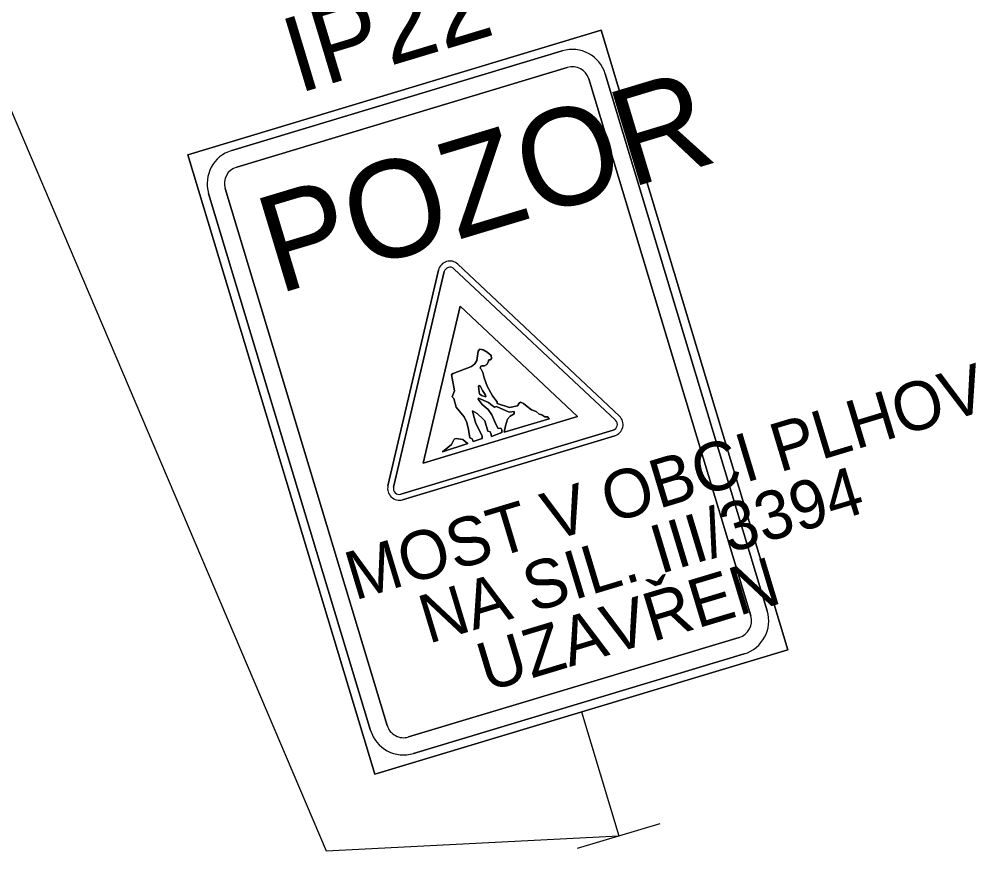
# Model space of a CAD drawing. Extents: x -688893 to -679983, y -1088371 to -1075771.
# Drawn here: x -686908 to -686243, y -1079689 to -1079111 of the extents above; entities that cross this region are included whole.
import ezdxf

# ---------------------------------------------------------------- set-up
doc = ezdxf.new("R2010")
doc.units = 0
for name, color, linetype in [('SDZ', 7, 'Continuous'), ('SDZ ozn', 7, 'Continuous'), ('SDZ plochy', 7, 'Continuous'), ('SDZ symbol', 7, 'Continuous')]:
    doc.layers.add(name, color=color, linetype=linetype)

msp = doc.modelspace()

# ---------------------------------------------------------------- linework, layer by layer
at = {"layer": 'SDZ'}
for p, q in [((-686790.82, -1079204.92), (-686503.59, -1079118.31)), ((-686503.59, -1079118.31), (-686373.67, -1079549.15)), ((-686760.36, -1079202.01), (-686530.58, -1079132.72)), ((-686756.9, -1079213.5), (-686527.12, -1079144.21)), ((-686500.67, -1079148.77), (-686388.08, -1079522.16)), ((-686512.16, -1079152.23), (-686399.57, -1079525.62)), ((-686660.9, -1079635.76), (-686790.82, -1079204.92)), ((-686652.33, -1079601.84), (-686764.92, -1079228.45)), ((-686663.82, -1079605.31), (-686776.41, -1079231.91)), ((-686603.16, -1079281.06), (-686490.86, -1079386.71)), ((-686603.06, -1079281.16), (-686603.06, -1079281.16)), ((-686651.78, -1079435.24), (-686616.6, -1079285.11)), ((-686612.59, -1079286.26), (-686647.9, -1079436.18)), ((-686612.56, -1079286.14), (-686612.56, -1079286.14)), ((-686493.57, -1079389.64), (-686605.87, -1079284.24)), ((-686601.66, -1079310.35), (-686627.36, -1079419.41)), ((-686519.95, -1079387.02), (-686601.66, -1079310.35)), ((-686589.05, -1079341.65), (-686589.59, -1079344.78)), ((-686587.79, -1079340.22), (-686589.05, -1079341.65)), ((-686585.56, -1079340.6), (-686587.79, -1079340.22)), ((-686582.72, -1079342.29), (-686585.56, -1079340.6)), ((-686589.87, -1079348.04), (-686591.29, -1079350.37)), ((-686589.59, -1079344.78), (-686589.87, -1079348.04)), ((-686580.1, -1079344.67), (-686582.72, -1079342.29)), ((-686582.09, -1079349.29), (-686581.53, -1079347.64)), ((-686581.53, -1079347.64), (-686580.51, -1079347.54)), ((-686580.51, -1079347.54), (-686579.71, -1079346.67)), ((-686579.71, -1079346.67), (-686580.1, -1079344.67)), ((-686593.71, -1079352.15), (-686606.41, -1079357.04)), ((-686591.29, -1079350.37), (-686593.71, -1079352.15)), ((-686587.65, -1079353.29), (-686587.23, -1079351.89)), ((-686586.97, -1079354.14), (-686587.65, -1079353.29)), ((-686587.23, -1079351.89), (-686586.45, -1079351.66)), ((-686585.89, -1079356.35), (-686586.97, -1079354.14)), ((-686586.45, -1079351.66), (-686584.73, -1079351.77)), ((-686584.73, -1079351.77), (-686583.1, -1079350.86)), ((-686583.1, -1079350.86), (-686582.09, -1079349.29)), ((-686606.41, -1079357.04), (-686607.65, -1079357.84)), ((-686607.65, -1079357.84), (-686605.48, -1079369.24)), ((-686584.77, -1079360.04), (-686585.89, -1079356.35)), ((-686582.77, -1079365.99), (-686584.77, -1079360.04)), ((-686588.26, -1079365.32), (-686588.86, -1079366.13)), ((-686588.86, -1079366.13), (-686588.39, -1079369.8)), ((-686587.38, -1079366.11), (-686588.26, -1079365.32)), ((-686585.93, -1079368.84), (-686587.38, -1079366.11)), ((-686579.11, -1079372.5), (-686582.77, -1079365.99)), ((-686605.48, -1079369.24), (-686607.2, -1079373.35)), ((-686607.2, -1079373.35), (-686606.01, -1079374.48)), ((-686606.01, -1079374.48), (-686604.39, -1079380.55)), ((-686588.98, -1079374.84), (-686588.71, -1079374.34)), ((-686586.34, -1079378.7), (-686588.98, -1079374.84)), ((-686588.71, -1079374.34), (-686581.88, -1079377.35)), ((-686588.39, -1079369.8), (-686588.17, -1079371.21)), ((-686588.17, -1079371.21), (-686586.74, -1079372.47)), ((-686586.74, -1079372.47), (-686583.75, -1079373.26)), ((-686584.21, -1079371.71), (-686585.93, -1079368.84)), ((-686583.75, -1079373.26), (-686584.21, -1079371.71)), ((-686576.96, -1079375.45), (-686579.11, -1079372.5)), ((-686604.39, -1079380.55), (-686602.16, -1079383.05)), ((-686582.14, -1079382.09), (-686586.34, -1079378.7)), ((-686581.88, -1079377.35), (-686580.19, -1079378.75)), ((-686580.19, -1079378.75), (-686577.74, -1079380.55)), ((-686577.74, -1079380.55), (-686576.19, -1079380.08)), ((-686575.91, -1079376.82), (-686576.96, -1079375.45)), ((-686576.19, -1079380.08), (-686567.4, -1079383.99)), ((-686575.75, -1079378.04), (-686575.91, -1079376.82)), ((-686567.31, -1079380.78), (-686575.75, -1079378.04)), ((-686561.76, -1079379.54), (-686567.31, -1079380.78)), ((-686560.62, -1079377.71), (-686561.76, -1079379.54)), ((-686559.57, -1079376.97), (-686560.62, -1079377.71)), ((-686557.56, -1079378.06), (-686559.57, -1079376.97)), ((-686554.86, -1079379.99), (-686557.56, -1079378.06)), ((-686551.85, -1079382.26), (-686554.86, -1079379.99)), ((-686627.36, -1079419.41), (-686519.95, -1079387.02)), ((-686602.16, -1079383.05), (-686598.82, -1079387.11)), ((-686598.82, -1079387.11), (-686596.95, -1079391.2)), ((-686592.38, -1079386.02), (-686592.87, -1079382.99)), ((-686592.87, -1079382.99), (-686589.78, -1079384.81)), ((-686590.63, -1079391.83), (-686592.38, -1079386.02)), ((-686589.78, -1079384.81), (-686585.61, -1079388.84)), ((-686579.56, -1079385.75), (-686582.14, -1079382.09)), ((-686577.4, -1079390.81), (-686579.56, -1079385.75)), ((-686566.78, -1079386.76), (-686568.69, -1079388.82)), ((-686567.4, -1079383.99), (-686563.93, -1079383.57)), ((-686563.91, -1079385.05), (-686566.78, -1079386.76)), ((-686563.93, -1079383.57), (-686563.91, -1079385.05)), ((-686548.74, -1079383.43), (-686551.85, -1079382.26)), ((-686546.68, -1079385.35), (-686548.74, -1079383.43)), ((-686544.84, -1079385.85), (-686546.68, -1079385.35)), ((-686542.76, -1079387.13), (-686544.84, -1079385.85)), ((-686540.84, -1079387.19), (-686542.76, -1079387.13)), ((-686539.6, -1079388.5), (-686540.84, -1079387.19)), ((-686596.95, -1079391.2), (-686595.68, -1079396.11)), ((-686586.33, -1079400.48), (-686590.63, -1079391.83)), ((-686585.61, -1079388.84), (-686584.42, -1079389.96)), ((-686584.42, -1079389.96), (-686582.26, -1079397.14)), ((-686575.28, -1079395.03), (-686577.4, -1079390.81)), ((-686571.07, -1079397.78), (-686539.6, -1079388.5)), ((-686570.04, -1079393.45), (-686571.07, -1079397.78)), ((-686568.69, -1079388.82), (-686570.04, -1079393.45)), ((-686642.79, -1079440.98), (-686495.18, -1079396.47)), ((-686641.55, -1079444.84), (-686494.07, -1079400.37)), ((-686595.68, -1079396.11), (-686594.82, -1079401.77)), ((-686586.19, -1079402.34), (-686586.33, -1079400.48)), ((-686582.26, -1079397.14), (-686580.8, -1079397.76)), ((-686580.8, -1079397.76), (-686580.32, -1079398.67)), ((-686580.32, -1079398.67), (-686579.67, -1079400.8)), ((-686579.67, -1079400.8), (-686572.48, -1079398)), ((-686573.11, -1079395.22), (-686575.28, -1079395.03)), ((-686572.56, -1079396.33), (-686573.11, -1079395.22)), ((-686572.48, -1079398), (-686572.56, -1079396.33)), ((-686613.87, -1079411.54), (-686596.15, -1079405.77)), ((-686607.58, -1079406.46), (-686610.13, -1079408.5)), ((-686606.01, -1079403.24), (-686607.58, -1079406.46)), ((-686605.16, -1079402.56), (-686606.01, -1079403.24)), ((-686603.99, -1079402.21), (-686605.16, -1079402.56)), ((-686602.85, -1079402.5), (-686603.99, -1079402.21)), ((-686599.73, -1079403.04), (-686602.85, -1079402.5)), ((-686597.78, -1079404.57), (-686599.73, -1079403.04)), ((-686596.15, -1079405.77), (-686597.78, -1079404.57)), ((-686594.82, -1079401.77), (-686593.31, -1079402.58)), ((-686593.31, -1079402.58), (-686592.53, -1079404.46)), ((-686592.53, -1079404.46), (-686586.19, -1079402.34)), ((-686610.13, -1079408.5), (-686613.87, -1079411.54)), ((-686407.59, -1079540.58), (-686637.37, -1079609.87)), ((-686373.67, -1079549.15), (-686660.9, -1079635.76)), ((-686404.13, -1079552.07), (-686633.91, -1079621.36)), ((-686517.29, -1079592.46), (-686491.3, -1079678.62)), ((-686520.03, -1079687.28), (-686462.58, -1079669.96))]:
    msp.add_line(p, q, dxfattribs=at)
msp.add_lwpolyline([(-687001.23, -1078968.55), (-686694.81, -1079689.08), (-686491.3, -1079678.62)], dxfattribs=at)
for centre, radius, start, end in [((-686523.65, -1079155.7), 24, 16.7805, 106.7805), ((-686523.65, -1079155.7), 12, 16.7805, 106.7805), ((-686753.43, -1079224.99), 24, 106.7805, 196.7805), ((-686753.43, -1079224.99), 12, 106.7805, 196.7805), ((-686608.71, -1079286.96), 8.1, 46.74959, 166.81141), ((-686608.64, -1079287.19), 4.05, 46.8148, 166.7462), ((-686496.41, -1079392.61), 8.1, 286.7805, 46.74959), ((-686496.34, -1079392.59), 4.05, 286.7805, 46.8148), ((-686643.89, -1079437.08), 8.1, 166.81141, 286.7805), ((-686643.95, -1079437.1), 4.05, 166.7462, 286.7805), ((-686411.06, -1079529.09), 12, 286.7805, 16.7805), ((-686411.06, -1079529.09), 24, 286.7805, 16.7805), ((-686640.84, -1079598.38), 24, 196.7805, 286.7805), ((-686640.84, -1079598.38), 12, 196.7805, 286.7805)]:
    msp.add_arc(centre, radius, start, end, dxfattribs=at)
at = {"layer": 'SDZ plochy'}
for p, q in [((-686503.59, -1079118.31), (-686790.82, -1079204.92)), ((-686373.67, -1079549.15), (-686503.59, -1079118.31)), ((-686530.58, -1079132.72), (-686760.36, -1079202.01)), ((-686760.36, -1079202.01), (-686530.58, -1079132.72)), ((-686756.9, -1079213.5), (-686527.12, -1079144.21)), ((-686527.12, -1079144.21), (-686756.9, -1079213.5)), ((-686388.08, -1079522.16), (-686500.67, -1079148.77)), ((-686500.67, -1079148.77), (-686388.08, -1079522.16)), ((-686512.16, -1079152.23), (-686399.57, -1079525.62)), ((-686399.57, -1079525.62), (-686512.16, -1079152.23)), ((-686790.82, -1079204.92), (-686660.9, -1079635.76)), ((-686652.33, -1079601.84), (-686764.92, -1079228.45)), ((-686764.92, -1079228.45), (-686652.33, -1079601.84)), ((-686776.41, -1079231.91), (-686663.82, -1079605.31)), ((-686663.82, -1079605.31), (-686776.41, -1079231.91)), ((-686603.16, -1079281.06), (-686490.86, -1079386.71)), ((-686490.86, -1079386.71), (-686603.16, -1079281.06)), ((-686651.78, -1079435.24), (-686616.6, -1079285.11)), ((-686616.6, -1079285.11), (-686651.78, -1079435.24)), ((-686612.59, -1079286.26), (-686647.9, -1079436.18)), ((-686647.9, -1079436.18), (-686612.59, -1079286.26)), ((-686493.57, -1079389.64), (-686605.87, -1079284.24)), ((-686605.87, -1079284.24), (-686493.57, -1079389.64)), ((-686627.36, -1079419.41), (-686601.66, -1079310.35)), ((-686601.66, -1079310.35), (-686627.36, -1079419.41)), ((-686601.66, -1079310.35), (-686519.95, -1079387.02)), ((-686519.95, -1079387.02), (-686601.66, -1079310.35)), ((-686589.05, -1079341.65), (-686589.59, -1079344.78)), ((-686589.59, -1079344.78), (-686589.05, -1079341.65)), ((-686587.79, -1079340.22), (-686589.05, -1079341.65)), ((-686589.05, -1079341.65), (-686587.79, -1079340.22)), ((-686585.56, -1079340.6), (-686587.79, -1079340.22)), ((-686587.79, -1079340.22), (-686585.56, -1079340.6)), ((-686582.72, -1079342.29), (-686585.56, -1079340.6)), ((-686585.56, -1079340.6), (-686582.72, -1079342.29)), ((-686589.87, -1079348.04), (-686591.29, -1079350.37)), ((-686591.29, -1079350.37), (-686589.87, -1079348.04)), ((-686589.59, -1079344.78), (-686589.87, -1079348.04)), ((-686589.87, -1079348.04), (-686589.59, -1079344.78)), ((-686580.1, -1079344.67), (-686582.72, -1079342.29)), ((-686582.72, -1079342.29), (-686580.1, -1079344.67)), ((-686582.09, -1079349.29), (-686581.53, -1079347.64)), ((-686581.53, -1079347.64), (-686582.09, -1079349.29)), ((-686581.53, -1079347.64), (-686580.51, -1079347.54)), ((-686580.51, -1079347.54), (-686581.53, -1079347.64)), ((-686580.51, -1079347.54), (-686579.71, -1079346.67)), ((-686579.71, -1079346.67), (-686580.51, -1079347.54)), ((-686579.71, -1079346.67), (-686580.1, -1079344.67)), ((-686580.1, -1079344.67), (-686579.71, -1079346.67)), ((-686593.71, -1079352.15), (-686606.41, -1079357.04)), ((-686606.41, -1079357.04), (-686593.71, -1079352.15)), ((-686591.29, -1079350.37), (-686593.71, -1079352.15)), ((-686593.71, -1079352.15), (-686591.29, -1079350.37)), ((-686587.65, -1079353.29), (-686587.23, -1079351.89)), ((-686587.23, -1079351.89), (-686587.65, -1079353.29)), ((-686586.97, -1079354.14), (-686587.65, -1079353.29)), ((-686587.65, -1079353.29), (-686586.97, -1079354.14)), ((-686587.23, -1079351.89), (-686586.45, -1079351.66)), ((-686586.45, -1079351.66), (-686587.23, -1079351.89)), ((-686585.89, -1079356.35), (-686586.97, -1079354.14)), ((-686586.97, -1079354.14), (-686585.89, -1079356.35)), ((-686586.45, -1079351.66), (-686584.73, -1079351.77)), ((-686584.73, -1079351.77), (-686586.45, -1079351.66)), ((-686584.73, -1079351.77), (-686583.1, -1079350.86)), ((-686583.1, -1079350.86), (-686584.73, -1079351.77)), ((-686583.1, -1079350.86), (-686582.09, -1079349.29)), ((-686582.09, -1079349.29), (-686583.1, -1079350.86)), ((-686606.41, -1079357.04), (-686607.65, -1079357.84)), ((-686607.65, -1079357.84), (-686606.41, -1079357.04)), ((-686607.65, -1079357.84), (-686605.48, -1079369.24)), ((-686605.48, -1079369.24), (-686607.65, -1079357.84)), ((-686584.77, -1079360.04), (-686585.89, -1079356.35)), ((-686585.89, -1079356.35), (-686584.77, -1079360.04)), ((-686582.77, -1079365.99), (-686584.77, -1079360.04)), ((-686584.77, -1079360.04), (-686582.77, -1079365.99)), ((-686588.86, -1079366.13), (-686588.26, -1079365.32)), ((-686588.26, -1079365.32), (-686588.86, -1079366.13)), ((-686588.39, -1079369.8), (-686588.86, -1079366.13)), ((-686588.86, -1079366.13), (-686588.39, -1079369.8)), ((-686588.26, -1079365.32), (-686587.38, -1079366.11)), ((-686587.38, -1079366.11), (-686588.26, -1079365.32)), ((-686587.38, -1079366.11), (-686585.93, -1079368.84)), ((-686585.93, -1079368.84), (-686587.38, -1079366.11)), ((-686579.11, -1079372.5), (-686582.77, -1079365.99)), ((-686582.77, -1079365.99), (-686579.11, -1079372.5)), ((-686605.48, -1079369.24), (-686607.2, -1079373.35)), ((-686607.2, -1079373.35), (-686605.48, -1079369.24)), ((-686607.2, -1079373.35), (-686606.01, -1079374.48)), ((-686606.01, -1079374.48), (-686607.2, -1079373.35)), ((-686606.01, -1079374.48), (-686604.39, -1079380.55)), ((-686604.39, -1079380.55), (-686606.01, -1079374.48)), ((-686588.98, -1079374.84), (-686588.71, -1079374.34)), ((-686588.71, -1079374.34), (-686588.98, -1079374.84)), ((-686586.34, -1079378.7), (-686588.98, -1079374.84)), ((-686588.98, -1079374.84), (-686586.34, -1079378.7)), ((-686588.71, -1079374.34), (-686581.88, -1079377.35)), ((-686581.88, -1079377.35), (-686588.71, -1079374.34)), ((-686588.17, -1079371.21), (-686588.39, -1079369.8)), ((-686588.39, -1079369.8), (-686588.17, -1079371.21)), ((-686586.74, -1079372.47), (-686588.17, -1079371.21)), ((-686588.17, -1079371.21), (-686586.74, -1079372.47)), ((-686583.75, -1079373.26), (-686586.74, -1079372.47)), ((-686586.74, -1079372.47), (-686583.75, -1079373.26)), ((-686585.93, -1079368.84), (-686584.21, -1079371.71)), ((-686584.21, -1079371.71), (-686585.93, -1079368.84)), ((-686584.21, -1079371.71), (-686583.75, -1079373.26)), ((-686583.75, -1079373.26), (-686584.21, -1079371.71)), ((-686576.96, -1079375.45), (-686579.11, -1079372.5)), ((-686579.11, -1079372.5), (-686576.96, -1079375.45)), ((-686604.39, -1079380.55), (-686602.16, -1079383.05)), ((-686602.16, -1079383.05), (-686604.39, -1079380.55)), ((-686582.14, -1079382.09), (-686586.34, -1079378.7)), ((-686586.34, -1079378.7), (-686582.14, -1079382.09)), ((-686581.88, -1079377.35), (-686580.19, -1079378.75)), ((-686580.19, -1079378.75), (-686581.88, -1079377.35)), ((-686580.19, -1079378.75), (-686577.74, -1079380.55)), ((-686577.74, -1079380.55), (-686580.19, -1079378.75)), ((-686577.74, -1079380.55), (-686576.19, -1079380.08)), ((-686576.19, -1079380.08), (-686577.74, -1079380.55)), ((-686575.91, -1079376.82), (-686576.96, -1079375.45)), ((-686576.96, -1079375.45), (-686575.91, -1079376.82)), ((-686576.19, -1079380.08), (-686567.4, -1079383.99)), ((-686567.4, -1079383.99), (-686576.19, -1079380.08)), ((-686575.75, -1079378.04), (-686575.91, -1079376.82)), ((-686575.91, -1079376.82), (-686575.75, -1079378.04)), ((-686567.31, -1079380.78), (-686575.75, -1079378.04)), ((-686575.75, -1079378.04), (-686567.31, -1079380.78)), ((-686561.76, -1079379.54), (-686567.31, -1079380.78)), ((-686567.31, -1079380.78), (-686561.76, -1079379.54)), ((-686560.62, -1079377.71), (-686561.76, -1079379.54)), ((-686561.76, -1079379.54), (-686560.62, -1079377.71)), ((-686559.57, -1079376.97), (-686560.62, -1079377.71)), ((-686560.62, -1079377.71), (-686559.57, -1079376.97)), ((-686557.56, -1079378.06), (-686559.57, -1079376.97)), ((-686559.57, -1079376.97), (-686557.56, -1079378.06)), ((-686554.86, -1079379.99), (-686557.56, -1079378.06)), ((-686557.56, -1079378.06), (-686554.86, -1079379.99)), ((-686551.85, -1079382.26), (-686554.86, -1079379.99)), ((-686554.86, -1079379.99), (-686551.85, -1079382.26)), ((-686519.95, -1079387.02), (-686627.36, -1079419.41)), ((-686627.36, -1079419.41), (-686519.95, -1079387.02)), ((-686602.16, -1079383.05), (-686598.82, -1079387.11)), ((-686598.82, -1079387.11), (-686602.16, -1079383.05)), ((-686598.82, -1079387.11), (-686596.95, -1079391.2)), ((-686596.95, -1079391.2), (-686598.82, -1079387.11)), ((-686592.38, -1079386.02), (-686592.87, -1079382.99)), ((-686592.87, -1079382.99), (-686589.78, -1079384.81)), ((-686589.78, -1079384.81), (-686592.87, -1079382.99)), ((-686592.87, -1079382.99), (-686592.38, -1079386.02)), ((-686590.63, -1079391.83), (-686592.38, -1079386.02)), ((-686592.38, -1079386.02), (-686590.63, -1079391.83)), ((-686589.78, -1079384.81), (-686585.61, -1079388.84)), ((-686585.61, -1079388.84), (-686589.78, -1079384.81)), ((-686579.56, -1079385.75), (-686582.14, -1079382.09)), ((-686582.14, -1079382.09), (-686579.56, -1079385.75)), ((-686577.4, -1079390.81), (-686579.56, -1079385.75)), ((-686579.56, -1079385.75), (-686577.4, -1079390.81)), ((-686566.78, -1079386.76), (-686568.69, -1079388.82)), ((-686568.69, -1079388.82), (-686566.78, -1079386.76)), ((-686567.4, -1079383.99), (-686563.93, -1079383.57)), ((-686563.93, -1079383.57), (-686567.4, -1079383.99)), ((-686563.91, -1079385.05), (-686566.78, -1079386.76)), ((-686566.78, -1079386.76), (-686563.91, -1079385.05)), ((-686563.93, -1079383.57), (-686563.91, -1079385.05)), ((-686563.91, -1079385.05), (-686563.93, -1079383.57)), ((-686548.74, -1079383.43), (-686551.85, -1079382.26)), ((-686551.85, -1079382.26), (-686548.74, -1079383.43)), ((-686546.68, -1079385.35), (-686548.74, -1079383.43)), ((-686548.74, -1079383.43), (-686546.68, -1079385.35)), ((-686544.84, -1079385.85), (-686546.68, -1079385.35)), ((-686546.68, -1079385.35), (-686544.84, -1079385.85)), ((-686542.76, -1079387.13), (-686544.84, -1079385.85)), ((-686544.84, -1079385.85), (-686542.76, -1079387.13)), ((-686540.84, -1079387.19), (-686542.76, -1079387.13)), ((-686542.76, -1079387.13), (-686540.84, -1079387.19)), ((-686539.6, -1079388.5), (-686540.84, -1079387.19)), ((-686540.84, -1079387.19), (-686539.6, -1079388.5)), ((-686596.95, -1079391.2), (-686595.68, -1079396.11)), ((-686595.68, -1079396.11), (-686596.95, -1079391.2)), ((-686586.33, -1079400.48), (-686590.63, -1079391.83)), ((-686590.63, -1079391.83), (-686586.33, -1079400.48)), ((-686585.61, -1079388.84), (-686584.42, -1079389.96)), ((-686584.42, -1079389.96), (-686585.61, -1079388.84)), ((-686584.42, -1079389.96), (-686582.26, -1079397.14)), ((-686582.26, -1079397.14), (-686584.42, -1079389.96)), ((-686575.28, -1079395.03), (-686577.4, -1079390.81)), ((-686577.4, -1079390.81), (-686575.28, -1079395.03)), ((-686571.07, -1079397.78), (-686539.6, -1079388.5)), ((-686539.6, -1079388.5), (-686571.07, -1079397.78)), ((-686570.04, -1079393.45), (-686571.07, -1079397.78)), ((-686571.07, -1079397.78), (-686570.04, -1079393.45)), ((-686568.69, -1079388.82), (-686570.04, -1079393.45)), ((-686570.04, -1079393.45), (-686568.69, -1079388.82)), ((-686642.79, -1079440.98), (-686495.18, -1079396.47)), ((-686495.18, -1079396.47), (-686642.79, -1079440.98)), ((-686494.07, -1079400.37), (-686641.55, -1079444.84)), ((-686641.55, -1079444.84), (-686494.07, -1079400.37)), ((-686595.68, -1079396.11), (-686594.82, -1079401.77)), ((-686594.82, -1079401.77), (-686595.68, -1079396.11)), ((-686586.19, -1079402.34), (-686586.33, -1079400.48)), ((-686586.33, -1079400.48), (-686586.19, -1079402.34)), ((-686582.26, -1079397.14), (-686580.8, -1079397.76)), ((-686580.8, -1079397.76), (-686582.26, -1079397.14)), ((-686580.8, -1079397.76), (-686580.32, -1079398.67)), ((-686580.32, -1079398.67), (-686580.8, -1079397.76)), ((-686580.32, -1079398.67), (-686579.67, -1079400.8)), ((-686579.67, -1079400.8), (-686580.32, -1079398.67)), ((-686579.67, -1079400.8), (-686572.48, -1079398)), ((-686572.48, -1079398), (-686579.67, -1079400.8)), ((-686573.11, -1079395.22), (-686575.28, -1079395.03)), ((-686575.28, -1079395.03), (-686573.11, -1079395.22)), ((-686572.56, -1079396.33), (-686573.11, -1079395.22)), ((-686573.11, -1079395.22), (-686572.56, -1079396.33)), ((-686572.48, -1079398), (-686572.56, -1079396.33)), ((-686572.56, -1079396.33), (-686572.48, -1079398)), ((-686613.87, -1079411.54), (-686596.15, -1079405.77)), ((-686596.15, -1079405.77), (-686613.87, -1079411.54)), ((-686607.58, -1079406.46), (-686610.13, -1079408.5)), ((-686610.13, -1079408.5), (-686607.58, -1079406.46)), ((-686606.01, -1079403.24), (-686607.58, -1079406.46)), ((-686607.58, -1079406.46), (-686606.01, -1079403.24)), ((-686605.16, -1079402.56), (-686606.01, -1079403.24)), ((-686606.01, -1079403.24), (-686605.16, -1079402.56)), ((-686603.99, -1079402.21), (-686605.16, -1079402.56)), ((-686605.16, -1079402.56), (-686603.99, -1079402.21)), ((-686602.85, -1079402.5), (-686603.99, -1079402.21)), ((-686603.99, -1079402.21), (-686602.85, -1079402.5)), ((-686599.73, -1079403.04), (-686602.85, -1079402.5)), ((-686602.85, -1079402.5), (-686599.73, -1079403.04)), ((-686597.78, -1079404.57), (-686599.73, -1079403.04)), ((-686599.73, -1079403.04), (-686597.78, -1079404.57)), ((-686596.15, -1079405.77), (-686597.78, -1079404.57)), ((-686597.78, -1079404.57), (-686596.15, -1079405.77)), ((-686594.82, -1079401.77), (-686593.31, -1079402.58)), ((-686593.31, -1079402.58), (-686594.82, -1079401.77)), ((-686593.31, -1079402.58), (-686592.53, -1079404.46)), ((-686592.53, -1079404.46), (-686593.31, -1079402.58)), ((-686592.53, -1079404.46), (-686586.19, -1079402.34)), ((-686586.19, -1079402.34), (-686592.53, -1079404.46)), ((-686610.13, -1079408.5), (-686613.87, -1079411.54)), ((-686613.87, -1079411.54), (-686610.13, -1079408.5)), ((-686407.59, -1079540.58), (-686637.37, -1079609.87)), ((-686637.37, -1079609.87), (-686407.59, -1079540.58)), ((-686660.9, -1079635.76), (-686373.67, -1079549.15)), ((-686633.91, -1079621.36), (-686404.13, -1079552.07)), ((-686404.13, -1079552.07), (-686633.91, -1079621.36))]:
    msp.add_line(p, q, dxfattribs=at)
for centre, radius, start, end in [((-686523.65, -1079155.7), 24, 16.7805, 106.7805), ((-686523.65, -1079155.7), 24, 16.7805, 106.7805), ((-686523.65, -1079155.7), 12, 16.7805, 106.7805), ((-686523.65, -1079155.7), 12, 16.7805, 106.7805), ((-686753.43, -1079224.99), 24, 106.7805, 196.7805), ((-686753.43, -1079224.99), 24, 106.7805, 196.7805), ((-686753.43, -1079224.99), 12, 106.7805, 196.7805), ((-686753.43, -1079224.99), 12, 106.7805, 196.7805), ((-686608.71, -1079286.96), 8.1, 46.74959, 166.81141), ((-686608.71, -1079286.96), 8.1, 46.74959, 166.81141), ((-686608.64, -1079287.19), 4.05, 46.8148, 166.7462), ((-686608.64, -1079287.19), 4.05, 46.8148, 166.7462), ((-686496.41, -1079392.61), 8.1, 286.7805, 46.74959), ((-686496.41, -1079392.61), 8.1, 286.7805, 46.74959), ((-686496.34, -1079392.59), 4.05, 286.7805, 46.8148), ((-686496.34, -1079392.59), 4.05, 286.7805, 46.8148), ((-686643.89, -1079437.08), 8.1, 166.81141, 286.7805), ((-686643.89, -1079437.08), 8.1, 166.81141, 286.7805), ((-686643.95, -1079437.1), 4.05, 166.7462, 286.7805), ((-686643.95, -1079437.1), 4.05, 166.7462, 286.7805), ((-686411.06, -1079529.09), 12, 286.7805, 16.7805), ((-686411.06, -1079529.09), 12, 286.7805, 16.7805), ((-686411.06, -1079529.09), 24, 286.7805, 16.7805), ((-686411.06, -1079529.09), 24, 286.7805, 16.7805), ((-686640.84, -1079598.38), 24, 196.7805, 286.7805), ((-686640.84, -1079598.38), 24, 196.7805, 286.7805), ((-686640.84, -1079598.38), 12, 196.7805, 286.7805), ((-686640.84, -1079598.38), 12, 196.7805, 286.7805)]:
    msp.add_arc(centre, radius, start, end, dxfattribs=at)

# ---------------------------------------------------------------- texts
at = {"layer": 'SDZ ozn'}
msp.add_text('IP22', height=52.5, rotation=16.7805, dxfattribs=at).set_placement((-686714.21, -1079162.51))
at = {"layer": 'SDZ symbol'}
for s, height, p in [('POZOR', 67.5, (-686728.32, -1079302.02)), ('MOST V OBCI PLHOV', 33.75, (-686674.9, -1079515.03)), ('NA SIL. III/3394', 33.75, (-686623.67, -1079545.2)), ('UZAVŘEN', 33.75, (-686583.23, -1079578.63))]:
    msp.add_text(s, height=height, rotation=16.7805, dxfattribs=at).set_placement(p)

doc.saveas('drawing.dxf')
